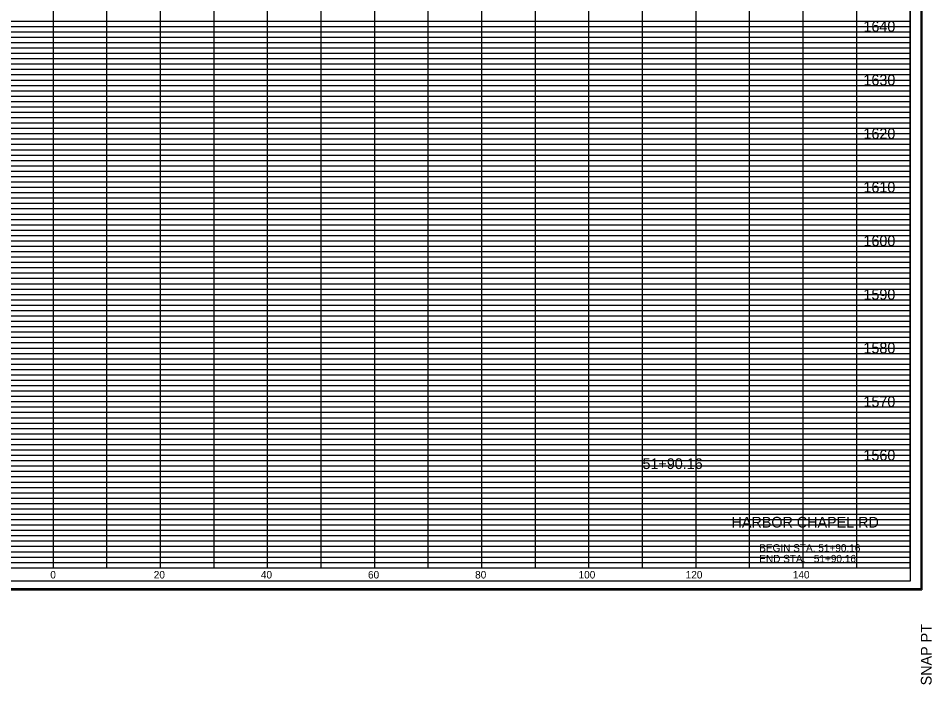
# Model space of a CAD drawing. Extents: x 980 to 1324, y 978 to 1767.
# Drawn here: x 1153.4 to 1324, y 1518.2 to 1642.5 of the extents above; entities that cross this region are included whole.
import ezdxf

# ---------------------------------------------------------------- set-up
doc = ezdxf.new("R2010")
doc.units = 0
for name, color, linetype in [('DESIGN - SHEET - Corner Text', 7, 'Continuous'), ('DESIGN - SHEET - Light Grid', 7, 'Continuous'), ('DESIGN - SHEET - Linework', 7, 'Continuous'), ('DESIGN - SHEET - Plot Shape', 7, 'Continuous'), ('DESIGN - TYPICAL - Finished Grade and Subgrade', 7, 'Continuous'), ('DESIGN - TYPICAL - Text', 7, 'Continuous')]:
    doc.layers.add(name, color=color, linetype=linetype)

# ---------------------------------------------------------------- blocks, each defined once
blk = doc.blocks.new('XSTSHT')
at = {"layer": 'DESIGN - SHEET - Light Grid'}
for p, q in [((8, 10.2), (16, 10.2)), ((8, 10.1), (16, 10.1)), ((16, 10.2), (24, 10.2)), ((16, 10.1), (24, 10.1)), ((24, 10.2), (32, 10.2)), ((24, 10.1), (32, 10.1)), ((8, 9.9), (16, 9.9)), ((16, 9.9), (24, 9.9)), ((24, 9.9), (32, 9.9)), ((8, 9.8), (16, 9.8)), ((16, 9.8), (24, 9.8)), ((24, 9.8), (32, 9.8)), ((8, 9.7), (16, 9.7)), ((8, 9.6), (16, 9.6)), ((16, 9.7), (24, 9.7)), ((16, 9.6), (24, 9.6)), ((24, 9.7), (32, 9.7)), ((24, 9.6), (32, 9.6)), ((8, 9.5), (16, 9.5)), ((8, 9.4), (16, 9.4)), ((16, 9.5), (24, 9.5)), ((16, 9.4), (24, 9.4)), ((24, 9.5), (32, 9.5)), ((24, 9.4), (32, 9.4)), ((8, 9.3), (16, 9.3)), ((16, 9.3), (24, 9.3)), ((24, 9.3), (32, 9.3)), ((8, 9.2), (16, 9.2)), ((8, 9.1), (16, 9.1)), ((16, 9.2), (24, 9.2)), ((16, 9.1), (24, 9.1)), ((24, 9.2), (32, 9.2)), ((24, 9.1), (32, 9.1)), ((8, 8.9), (16, 8.9)), ((16, 8.9), (24, 8.9)), ((24, 8.9), (32, 8.9)), ((8, 8.8), (16, 8.8)), ((8, 8.7), (16, 8.7)), ((16, 8.8), (24, 8.8)), ((16, 8.7), (24, 8.7)), ((24, 8.8), (32, 8.8)), ((24, 8.7), (32, 8.7)), ((8, 8.6), (16, 8.6)), ((16, 8.6), (24, 8.6)), ((24, 8.6), (32, 8.6)), ((8, 8.5), (16, 8.5)), ((8, 8.4), (16, 8.4)), ((16, 8.5), (24, 8.5)), ((16, 8.4), (24, 8.4)), ((24, 8.5), (32, 8.5)), ((24, 8.4), (32, 8.4)), ((8, 8.3), (16, 8.3)), ((8, 8.2), (16, 8.2)), ((16, 8.3), (24, 8.3)), ((16, 8.2), (24, 8.2)), ((24, 8.3), (32, 8.3)), ((24, 8.2), (32, 8.2)), ((8, 8.1), (16, 8.1)), ((16, 8.1), (24, 8.1)), ((24, 8.1), (32, 8.1)), ((8, 7.9), (16, 7.9)), ((16, 7.9), (24, 7.9)), ((24, 7.9), (32, 7.9)), ((8, 7.8), (16, 7.8)), ((8, 7.7), (16, 7.7)), ((16, 7.8), (24, 7.8)), ((16, 7.7), (24, 7.7)), ((24, 7.8), (32, 7.8)), ((24, 7.7), (32, 7.7)), ((8, 7.6), (16, 7.6)), ((16, 7.6), (24, 7.6)), ((24, 7.6), (32, 7.6)), ((8, 7.5), (16, 7.5)), ((8, 7.4), (16, 7.4)), ((16, 7.5), (24, 7.5)), ((16, 7.4), (24, 7.4)), ((24, 7.5), (32, 7.5)), ((24, 7.4), (32, 7.4)), ((8, 7.3), (16, 7.3)), ((8, 7.2), (16, 7.2)), ((16, 7.3), (24, 7.3)), ((16, 7.2), (24, 7.2)), ((24, 7.3), (32, 7.3)), ((24, 7.2), (32, 7.2)), ((8, 7.1), (16, 7.1)), ((16, 7.1), (24, 7.1)), ((24, 7.1), (32, 7.1)), ((8, 6.9), (16, 6.9)), ((16, 6.9), (24, 6.9)), ((24, 6.9), (32, 6.9)), ((8, 6.8), (16, 6.8)), ((8, 6.7), (16, 6.7)), ((16, 6.8), (24, 6.8)), ((16, 6.7), (24, 6.7)), ((24, 6.8), (32, 6.8)), ((24, 6.7), (32, 6.7)), ((8, 6.6), (16, 6.6)), ((8, 6.5), (16, 6.5)), ((16, 6.6), (24, 6.6)), ((16, 6.5), (24, 6.5)), ((24, 6.6), (32, 6.6)), ((24, 6.5), (32, 6.5)), ((8, 6.4), (16, 6.4)), ((16, 6.4), (24, 6.4)), ((24, 6.4), (32, 6.4)), ((8, 6.3), (16, 6.3)), ((8, 6.2), (16, 6.2)), ((16, 6.3), (24, 6.3)), ((16, 6.2), (24, 6.2)), ((24, 6.3), (32, 6.3)), ((24, 6.2), (32, 6.2)), ((8, 6.1), (16, 6.1)), ((16, 6.1), (24, 6.1)), ((24, 6.1), (32, 6.1)), ((8, 5.9), (16, 5.9)), ((8, 5.8), (16, 5.8)), ((16, 5.9), (24, 5.9)), ((16, 5.8), (24, 5.8)), ((24, 5.9), (32, 5.9)), ((24, 5.8), (32, 5.8)), ((8, 5.7), (16, 5.7)), ((16, 5.7), (24, 5.7)), ((24, 5.7), (32, 5.7)), ((8, 5.6), (16, 5.6)), ((8, 5.5), (16, 5.5)), ((16, 5.6), (24, 5.6)), ((16, 5.5), (24, 5.5)), ((24, 5.6), (32, 5.6)), ((24, 5.5), (32, 5.5)), ((8, 5.4), (16, 5.4)), ((8, 5.3), (16, 5.3)), ((16, 5.4), (24, 5.4)), ((16, 5.3), (24, 5.3)), ((24, 5.4), (32, 5.4)), ((24, 5.3), (32, 5.3)), ((8, 5.2), (16, 5.2)), ((16, 5.2), (24, 5.2)), ((24, 5.2), (32, 5.2)), ((8, 5.1), (16, 5.1)), ((16, 5.1), (24, 5.1)), ((24, 5.1), (32, 5.1)), ((8, 4.9), (16, 4.9)), ((8, 4.8), (16, 4.8)), ((16, 4.9), (24, 4.9)), ((16, 4.8), (24, 4.8)), ((24, 4.9), (32, 4.9)), ((24, 4.8), (32, 4.8)), ((8, 4.7), (16, 4.7)), ((16, 4.7), (24, 4.7)), ((24, 4.7), (32, 4.7)), ((8, 4.6), (16, 4.6)), ((8, 4.5), (16, 4.5)), ((16, 4.6), (24, 4.6)), ((16, 4.5), (24, 4.5)), ((24, 4.6), (32, 4.6)), ((24, 4.5), (32, 4.5)), ((8, 4.4), (16, 4.4)), ((8, 4.3), (16, 4.3)), ((16, 4.4), (24, 4.4)), ((16, 4.3), (24, 4.3)), ((24, 4.4), (32, 4.4)), ((24, 4.3), (32, 4.3)), ((8, 4.2), (16, 4.2)), ((8, 4.1), (16, 4.1)), ((16, 4.2), (24, 4.2)), ((16, 4.1), (24, 4.1)), ((24, 4.2), (32, 4.2)), ((24, 4.1), (32, 4.1)), ((8, 3.9), (16, 3.9)), ((8, 3.8), (16, 3.8)), ((16, 3.9), (24, 3.9)), ((16, 3.8), (24, 3.8)), ((24, 3.9), (32, 3.9)), ((24, 3.8), (32, 3.8)), ((8, 3.7), (16, 3.7)), ((8, 3.6), (16, 3.6)), ((16, 3.7), (24, 3.7)), ((16, 3.6), (24, 3.6)), ((24, 3.7), (32, 3.7)), ((24, 3.6), (32, 3.6)), ((8, 3.5), (16, 3.5)), ((16, 3.5), (24, 3.5)), ((24, 3.5), (32, 3.5)), ((8, 3.4), (16, 3.4)), ((8, 3.3), (16, 3.3)), ((16, 3.4), (24, 3.4)), ((16, 3.3), (24, 3.3)), ((24, 3.4), (32, 3.4)), ((24, 3.3), (32, 3.3)), ((8, 3.2), (16, 3.2)), ((8, 3.1), (16, 3.1)), ((16, 3.2), (24, 3.2)), ((16, 3.1), (24, 3.1)), ((24, 3.2), (32, 3.2)), ((24, 3.1), (32, 3.1)), ((8, 2.9), (16, 2.9)), ((16, 2.9), (24, 2.9)), ((24, 2.9), (32, 2.9)), ((8, 2.8), (16, 2.8)), ((16, 2.8), (24, 2.8)), ((24, 2.8), (32, 2.8)), ((8, 2.7), (16, 2.7)), ((8, 2.6), (16, 2.6)), ((16, 2.7), (24, 2.7)), ((16, 2.6), (24, 2.6)), ((24, 2.7), (32, 2.7)), ((24, 2.6), (32, 2.6)), ((8, 2.5), (16, 2.5)), ((8, 2.4), (16, 2.4)), ((16, 2.5), (24, 2.5)), ((16, 2.4), (24, 2.4)), ((24, 2.5), (32, 2.5)), ((24, 2.4), (32, 2.4)), ((8, 2.3), (16, 2.3)), ((16, 2.3), (24, 2.3)), ((24, 2.3), (32, 2.3)), ((8, 2.2), (16, 2.2)), ((8, 2.1), (16, 2.1)), ((16, 2.2), (24, 2.2)), ((16, 2.1), (24, 2.1)), ((24, 2.2), (32, 2.2)), ((24, 2.1), (32, 2.1)), ((8, 1.9), (16, 1.9)), ((16, 1.9), (24, 1.9)), ((24, 1.9), (32, 1.9)), ((8, 1.8), (16, 1.8)), ((16, 1.8), (24, 1.8)), ((24, 1.8), (32, 1.8)), ((8, 1.7), (16, 1.7)), ((8, 1.6), (16, 1.6)), ((16, 1.7), (24, 1.7)), ((16, 1.6), (24, 1.6)), ((24, 1.7), (32, 1.7)), ((24, 1.6), (32, 1.6)), ((8, 1.5), (16, 1.5)), ((8, 1.4), (16, 1.4)), ((16, 1.5), (24, 1.5)), ((16, 1.4), (24, 1.4)), ((24, 1.5), (32, 1.5)), ((24, 1.4), (32, 1.4)), ((8, 1.3), (16, 1.3)), ((8, 1.2), (16, 1.2)), ((16, 1.3), (24, 1.3)), ((16, 1.2), (24, 1.2)), ((24, 1.3), (32, 1.3)), ((24, 1.2), (32, 1.2)), ((8, 1.1), (16, 1.1)), ((16, 1.1), (24, 1.1)), ((24, 1.1), (32, 1.1)), ((8, 0.9), (16, 0.9)), ((16, 0.9), (24, 0.9)), ((24, 0.9), (32, 0.9)), ((8, 0.8), (16, 0.8)), ((8, 0.7), (16, 0.7)), ((16, 0.8), (24, 0.8)), ((16, 0.7), (24, 0.7)), ((24, 0.8), (32, 0.8)), ((24, 0.7), (32, 0.7)), ((8, 0.6), (16, 0.6)), ((16, 0.6), (24, 0.6)), ((24, 0.6), (32, 0.6)), ((8, 0.5), (16, 0.5)), ((8, 0.4), (16, 0.4)), ((16, 0.5), (24, 0.5)), ((16, 0.4), (24, 0.4)), ((24, 0.5), (32, 0.5)), ((24, 0.4), (32, 0.4)), ((8, 0.3), (16, 0.3)), ((8, 0.2), (16, 0.2)), ((16, 0.3), (24, 0.3)), ((16, 0.2), (24, 0.2)), ((24, 0.3), (32, 0.3)), ((24, 0.2), (32, 0.2)), ((8, 0.1), (16, 0.1)), ((16, 0.1), (24, 0.1)), ((24, 0.1), (32, 0.1))]:
    blk.add_line(p, q, dxfattribs=at)
at = {"layer": 'DESIGN - SHEET - Linework'}
for p, q in [((32.217, 21.414), (32.217, -0.414)), ((16, 0), (16, 21)), ((17, 0), (17, 21)), ((18, 0), (18, 21)), ((19, 0), (19, 21)), ((20, 0), (20, 21)), ((21, 0), (21, 21)), ((22, 0), (22, 21)), ((23, 0), (23, 21)), ((24, 0), (24, 21)), ((25, 0), (25, 21)), ((26, 0), (26, 21)), ((27, 0), (27, 21)), ((28, 0), (28, 20)), ((29, 0), (29, 20)), ((30, 0), (30, 20)), ((31, 0), (31, 20)), ((0, 10), (32, 10)), ((0, 9), (32, 9)), ((0, 8), (32, 8)), ((0, 7), (32, 7)), ((0, 6), (32, 6)), ((0, 5), (32, 5)), ((0, 4), (32, 4)), ((0, 3), (32, 3)), ((0, 2), (32, 2)), ((0, 1), (32, 1)), ((-1.823, -0.414), (32.217, -0.414))]:
    blk.add_line(p, q, dxfattribs=at)
blk.add_lwpolyline([(0, 21), (0, 0), (32, 0), (32, 21), (0, 21)], dxfattribs=at)
at = {"layer": 'DESIGN - SHEET - Plot Shape'}
for points in [[(-1.803, 21.394), (32.197, 21.394), (32.197, -0.394), (-1.803, -0.394)], [(-0.85, 21), (32, 21), (32, -0.25), (-0.85, -0.25)]]:
    blk.add_lwpolyline(points, close=True, dxfattribs=at)
at = {"layer": 'DESIGN - SHEET - Corner Text'}
blk.add_text('SNAP PT  ', height=0.2, rotation=90, dxfattribs=at).set_placement((32.397, -2.194))

msp = doc.modelspace()

# ---------------------------------------------------------------- linework, layer by layer
at = {"layer": 'DESIGN - SHEET - Plot Shape'}
msp.add_lwpolyline([(991.5, 1750), (1320, 1750), (1320, 1537.5), (991.5, 1537.5)], close=True, dxfattribs=at)

# ---------------------------------------------------------------- block references
at = {"layer": 'DESIGN - TYPICAL - Finished Grade and Subgrade', "xscale": 10, "yscale": 10}
msp.add_blockref('XSTSHT', (1000, 1540), dxfattribs=at)

# ---------------------------------------------------------------- texts
at = {"layer": 'DESIGN - SHEET - Corner Text'}
for s, height, p in [('1640', 2, (1311.25, 1640)), ('1630', 2, (1311.25, 1630)), ('1620', 2, (1311.25, 1620)), ('1610', 2, (1311.25, 1610)), ('1600', 2, (1311.25, 1600)), ('1590', 2, (1311.25, 1590)), ('1580', 2, (1311.25, 1580)), ('1570', 2, (1311.25, 1570)), ('1560', 2, (1311.25, 1560)), ('HARBOR CHAPEL RD', 2, (1286.63, 1547.5)), ('BEGIN STA. 51+90.16', 1.4, (1291.79, 1543)), ('END STA.   51+90.16', 1.4, (1291.79, 1541)), ('0', 1.4, (1159.42, 1538)), ('0', 1.4, (1159.42, 1538)), ('20', 1.4, (1178.74, 1538)), ('40', 1.4, (1198.74, 1538)), ('60', 1.4, (1218.74, 1538)), ('80', 1.4, (1238.74, 1538)), ('100', 1.4, (1258.06, 1538)), ('120', 1.4, (1278.06, 1538)), ('140', 1.4, (1298.06, 1538))]:
    msp.add_text(s, height=height, dxfattribs=at).set_placement(p)
at = {"layer": 'DESIGN - TYPICAL - Text'}
msp.add_text('51+90.16', height=2, dxfattribs=at).set_placement((1270, 1558.42))

doc.saveas('drawing.dxf')
